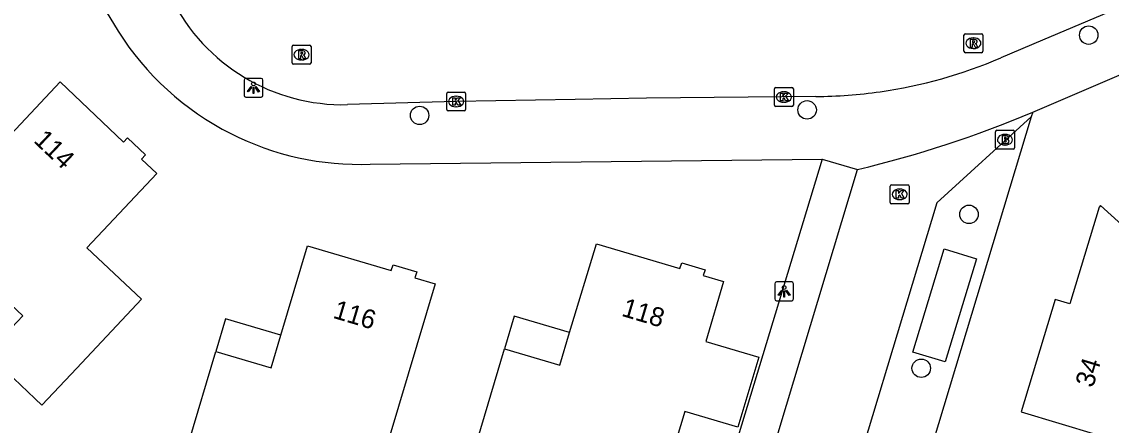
# Model space of a CAD drawing. Extents: x 157767 to 159171, y 387842 to 389425.
# Drawn here: x 158068.4 to 158126.1, y 388608.8 to 388630.1 of the extents above; entities that cross this region are included whole.
import ezdxf

# ---------------------------------------------------------------- set-up
doc = ezdxf.new("R2010")
doc.units = 0
for name, color, linetype in [('IMGEO_Boom', 7, 'Continuous'), ('IMGEO_Brandkraan', 7, 'Continuous'), ('IMGEO_Kolk', 7, 'Continuous'), ('IMGEO_Lichtpunt', 7, 'Continuous'), ('IMGEO_Pand', 7, 'Continuous'), ('IMGEO_Pand_nummerreeks', 7, 'Continuous'), ('IMGEO_Pand_overbouw', 7, 'Continuous'), ('IMGEO_Rijbaan_lokaal_open', 7, 'Continuous'), ('IMGEO_Rioolput', 7, 'Continuous'), ('IMGEO_Voetpad_open', 7, 'Continuous')]:
    doc.layers.add(name, color=color, linetype=linetype)

msp = doc.modelspace()

# ---------------------------------------------------------------- linework, layer by layer
at = {"layer": 'IMGEO_Boom'}
for centre in [(158124.95, 388629.419), (158089.511, 388625.171), (158110.036, 388625.462), (158118.608, 388619.933), (158116.078, 388611.787)]:
    msp.add_circle(centre, 0.489, dxfattribs=at)
at = {"layer": 'IMGEO_Brandkraan'}
for p, q in [((158120.014, 388623.457), (158120.014, 388624.309)), ((158120.089, 388624.383), (158120.941, 388624.383)), ((158120.502, 388624.163), (158120.527, 388624.163)), ((158121.015, 388624.309), (158121.015, 388623.457)), ((158120.941, 388623.383), (158120.089, 388623.383)), ((158120.525, 388623.603), (158120.5, 388623.603))]:
    msp.add_line(p, q, dxfattribs=at)
for points in [[(158120.014, 388623.457), (158120.014, 388624.309)], [(158120.089, 388624.383), (158120.941, 388624.383)], [(158120.362, 388624.083), (158120.362, 388623.683), (158120.575, 388623.683)], [(158120.593, 388624.083), (158120.362, 388624.083)], [(158120.541, 388624.002), (158120.487, 388624.002), (158120.487, 388623.926)], [(158120.487, 388623.926), (158120.54, 388623.926)], [(158121.015, 388624.309), (158121.015, 388623.457)], [(158120.941, 388623.383), (158120.089, 388623.383)], [(158120.549, 388623.85), (158120.487, 388623.85), (158120.487, 388623.769)], [(158120.487, 388623.769), (158120.549, 388623.769)]]:
    msp.add_lwpolyline(points, dxfattribs=at)
for centre, radius, start, end in [((158120.091, 388624.307), 0.0765, 91.55205, 178.44795), ((158120.091, 388624.307), 0.0765, 91.55205, 178.44795), ((158120.542, 388623.964), 0.0379, 267.82845, 90.93552), ((158120.597, 388623.938), 0.145, 59.4692, 91.53667), ((158120.622, 388623.985), 0.0922, 285.51372, 58.15012), ((158120.939, 388624.307), 0.0765, 1.55205, 88.44795), ((158120.939, 388624.307), 0.0765, 1.55205, 88.44795), ((158120.091, 388623.459), 0.0765, 181.55205, 268.44795), ((158120.091, 388623.459), 0.0765, 181.55205, 268.44795), ((158120.55, 388623.809), 0.0404, 269.87594, 90.50774), ((158120.581, 388623.934), 0.251, 268.66757, 293.53466), ((158120.627, 388623.793), 0.105, 301.31148, 78.98903), ((158120.939, 388623.459), 0.0765, 271.55205, 358.44795), ((158120.939, 388623.459), 0.0765, 271.55205, 358.44795)]:
    msp.add_arc(centre, radius, start, end, dxfattribs=at)
for centre, major_axis, ratio, start_param, end_param in [((158120.501, 388623.883), (-0.387, 0.002), 0.722429, 4.712389, 7.853982), ((158120.526, 388623.883), (-0.39, 0.002), 0.717154, 1.570796, 4.712389)]:
    msp.add_ellipse(centre, major_axis=major_axis, ratio=ratio, start_param=start_param, end_param=end_param, dxfattribs=at)
at = {"layer": 'IMGEO_Kolk'}
for p, q in [((158090.946, 388625.48), (158090.946, 388626.332)), ((158091.021, 388626.406), (158091.873, 388626.406)), ((158091.947, 388626.332), (158091.947, 388625.48)), ((158108.304, 388625.718), (158108.304, 388626.57)), ((158108.379, 388626.644), (158109.231, 388626.644)), ((158108.792, 388626.424), (158108.817, 388626.424)), ((158109.305, 388626.57), (158109.305, 388625.718)), ((158091.434, 388626.186), (158091.459, 388626.186)), ((158108.815, 388625.864), (158108.79, 388625.864)), ((158091.873, 388625.406), (158091.021, 388625.406)), ((158091.457, 388625.626), (158091.432, 388625.626)), ((158109.231, 388625.644), (158108.379, 388625.644)), ((158114.436, 388620.564), (158114.436, 388621.416)), ((158114.511, 388621.49), (158115.363, 388621.49)), ((158114.924, 388621.27), (158114.949, 388621.27)), ((158115.437, 388621.416), (158115.437, 388620.564)), ((158115.363, 388620.49), (158114.511, 388620.49)), ((158114.947, 388620.71), (158114.922, 388620.71))]:
    msp.add_line(p, q, dxfattribs=at)
for points in [[(158090.946, 388625.48), (158090.946, 388626.332)], [(158091.021, 388626.406), (158091.873, 388626.406)], [(158091.947, 388626.332), (158091.947, 388625.48)], [(158108.304, 388625.718), (158108.304, 388626.57)], [(158108.379, 388626.644), (158109.231, 388626.644)], [(158108.625, 388626.344), (158108.748, 388626.344), (158108.748, 388626.193), (158108.878, 388626.344), (158109.042, 388626.344), (158108.896, 388626.193), (158109.049, 388625.944), (158108.897, 388625.944), (158108.812, 388626.108), (158108.748, 388626.041), (158108.748, 388625.944), (158108.625, 388625.944), (158108.625, 388626.344)], [(158109.305, 388626.57), (158109.305, 388625.718)], [(158091.267, 388626.106), (158091.39, 388626.106), (158091.39, 388625.955), (158091.52, 388626.106), (158091.684, 388626.106), (158091.538, 388625.955), (158091.691, 388625.706), (158091.539, 388625.706), (158091.454, 388625.87), (158091.39, 388625.803), (158091.39, 388625.706), (158091.267, 388625.706), (158091.267, 388626.106)], [(158091.873, 388625.406), (158091.021, 388625.406)], [(158109.231, 388625.644), (158108.379, 388625.644)], [(158114.436, 388620.564), (158114.436, 388621.416)], [(158114.511, 388621.49), (158115.363, 388621.49)], [(158114.757, 388621.19), (158114.88, 388621.19), (158114.88, 388621.039), (158115.01, 388621.19), (158115.174, 388621.19), (158115.028, 388621.039), (158115.181, 388620.79), (158115.029, 388620.79), (158114.944, 388620.954), (158114.88, 388620.887), (158114.88, 388620.79), (158114.757, 388620.79), (158114.757, 388621.19)], [(158115.437, 388621.416), (158115.437, 388620.564)], [(158115.363, 388620.49), (158114.511, 388620.49)]]:
    msp.add_lwpolyline(points, dxfattribs=at)
for centre, start, end in [((158091.023, 388626.33), 91.55205, 178.44795), ((158091.023, 388626.33), 91.55205, 178.44795), ((158091.871, 388626.33), 1.55205, 88.44795), ((158091.871, 388626.33), 1.55205, 88.44795), ((158108.381, 388626.568), 91.55205, 178.44795), ((158108.381, 388626.568), 91.55205, 178.44795), ((158109.229, 388626.568), 1.55205, 88.44795), ((158109.229, 388626.568), 1.55205, 88.44795), ((158108.381, 388625.72), 181.55205, 268.44795), ((158108.381, 388625.72), 181.55205, 268.44795), ((158109.229, 388625.72), 271.55205, 358.44795), ((158109.229, 388625.72), 271.55205, 358.44795), ((158091.023, 388625.482), 181.55205, 268.44795), ((158091.023, 388625.482), 181.55205, 268.44795), ((158091.871, 388625.482), 271.55205, 358.44795), ((158091.871, 388625.482), 271.55205, 358.44795), ((158114.513, 388621.414), 91.55205, 178.44795), ((158114.513, 388621.414), 91.55205, 178.44795), ((158115.361, 388621.414), 1.55205, 88.44795), ((158115.361, 388621.414), 1.55205, 88.44795), ((158114.513, 388620.566), 181.55205, 268.44795), ((158114.513, 388620.566), 181.55205, 268.44795), ((158115.361, 388620.566), 271.55205, 358.44795), ((158115.361, 388620.566), 271.55205, 358.44795)]:
    msp.add_arc(centre, 0.0765, start, end, dxfattribs=at)
for centre, major_axis, ratio, start_param, end_param in [((158108.791, 388626.144), (-0.387, 0.002), 0.722429, 4.712389, 7.853982), ((158108.816, 388626.144), (-0.39, 0.002), 0.717154, 1.570796, 4.712389), ((158091.433, 388625.906), (-0.387, 0.002), 0.722429, 4.712389, 7.853982), ((158091.458, 388625.906), (-0.39, 0.002), 0.717154, 1.570796, 4.712389), ((158114.923, 388620.99), (-0.387, 0.002), 0.722429, 4.712389, 7.853982), ((158114.948, 388620.99), (-0.39, 0.002), 0.717154, 1.570796, 4.712389)]:
    msp.add_ellipse(centre, major_axis=major_axis, ratio=ratio, start_param=start_param, end_param=end_param, dxfattribs=at)
at = {"layer": 'IMGEO_Lichtpunt'}
for p, q in [((158080.214, 388627.036), (158080.214, 388626.229)), ((158080.214, 388627.036), (158080.214, 388626.229)), ((158081.116, 388627.131), (158080.308, 388627.131)), ((158081.116, 388627.131), (158080.308, 388627.131)), ((158081.21, 388626.229), (158081.21, 388627.036)), ((158081.21, 388626.229), (158081.21, 388627.036)), ((158080.308, 388626.135), (158081.116, 388626.135)), ((158080.308, 388626.135), (158081.116, 388626.135)), ((158108.318, 388616.261), (158108.318, 388615.454)), ((158108.318, 388616.261), (158108.318, 388615.454)), ((158109.22, 388616.356), (158108.412, 388616.356)), ((158109.22, 388616.356), (158108.412, 388616.356)), ((158109.314, 388615.454), (158109.314, 388616.261)), ((158109.314, 388615.454), (158109.314, 388616.261)), ((158108.412, 388615.36), (158109.22, 388615.36)), ((158108.412, 388615.36), (158109.22, 388615.36))]:
    msp.add_line(p, q, dxfattribs=at)
for points in [[(158080.588, 388626.7), (158080.627, 388626.672), (158080.439, 388626.41), (158080.401, 388626.437), (158080.588, 388626.7)], [(158080.69, 388626.652), (158080.737, 388626.652), (158080.737, 388626.33), (158080.69, 388626.33), (158080.69, 388626.652)], [(158080.8, 388626.672), (158080.838, 388626.699), (158081.025, 388626.437), (158080.986, 388626.409), (158080.8, 388626.672)], [(158108.692, 388615.925), (158108.731, 388615.897), (158108.543, 388615.635), (158108.505, 388615.662), (158108.692, 388615.925)], [(158108.794, 388615.877), (158108.841, 388615.877), (158108.841, 388615.555), (158108.794, 388615.555), (158108.794, 388615.877)], [(158108.904, 388615.897), (158108.942, 388615.924), (158109.129, 388615.662), (158109.09, 388615.634), (158108.904, 388615.897)]]:
    msp.add_lwpolyline(points, dxfattribs=at)
for centre in [(158080.713, 388626.834), (158108.817, 388616.059)]:
    msp.add_circle(centre, 0.0994, dxfattribs=at)
for centre, start, end in [((158080.308, 388627.036), 90, 180), ((158080.308, 388627.036), 90, 180), ((158081.116, 388627.036), 0, 90), ((158081.116, 388627.036), 0, 90), ((158080.308, 388626.229), 180, 270), ((158080.308, 388626.229), 180, 270), ((158081.116, 388626.229), 270, 0), ((158081.116, 388626.229), 270, 360), ((158108.412, 388616.261), 90, 180), ((158108.412, 388616.261), 90, 180), ((158109.22, 388616.261), 0, 90), ((158109.22, 388616.261), 0, 90), ((158108.412, 388615.454), 180, 270), ((158108.412, 388615.454), 180, 270), ((158109.22, 388615.454), 270, 0), ((158109.22, 388615.454), 270, 360)]:
    msp.add_arc(centre, 0.0946, start, end, dxfattribs=at)
at = {"layer": 'IMGEO_Pand'}
for points in [[(158067.64, 388611.59), (158067.598, 388613.613), (158068.491, 388614.561), (158065.977, 388616.929), (158062.894, 388613.658), (158058.049, 388618.224), (158060.19, 388620.454), (158063.653, 388624.06), (158065.8, 388621.999), (158067.059, 388623.331), (158070.47, 388626.939), (158073.821, 388623.759), (158074.041, 388623.991), (158074.994, 388623.089), (158074.774, 388622.857), (158075.586, 388622.087), (158071.89, 388618.165), (158074.785, 388615.436), (158071.356, 388611.798), (158069.503, 388609.833), (158067.64, 388611.59)], [(158132.014, 388603.229), (158132.651, 388605.327), (158133.533, 388608.235), (158131.528, 388608.844), (158132.654, 388612.554), (158131.877, 388612.79), (158132.331, 388614.286), (158125.578, 388620.401), (158125.498, 388620.309), (158123.945, 388615.198), (158123.177, 388615.431), (158121.373, 388609.487), (158125.364, 388608.277), (158126.349, 388607.978), (158125.508, 388605.204)], [(158076.409, 388604.909), (158077.293, 388607.881), (158078.719, 388612.673), (158081.643, 388611.804), (158082.157, 388613.529), (158083.569, 388618.273), (158088.009, 388616.965), (158088.103, 388617.258), (158089.358, 388616.898), (158089.258, 388616.577), (158090.34, 388616.259), (158088.902, 388611.471), (158087.362, 388606.343), (158082.858, 388607.684), (158081.574, 388603.371), (158076.409, 388604.909)], [(158094.472, 388604.207), (158093.645, 388601.415), (158090.868, 388602.238), (158091.697, 388605.035), (158094.005, 388612.821), (158096.93, 388611.955), (158097.451, 388613.678), (158098.871, 388618.376), (158103.3, 388617.065), (158103.399, 388617.364), (158104.63, 388616.998), (158104.538, 388616.692), (158105.609, 388616.37), (158104.665, 388613.208), (158107.469, 388612.371), (158106.361, 388608.662), (158103.557, 388609.499), (158102.649, 388606.457), (158098.15, 388607.799), (158096.865, 388603.493), (158094.472, 388604.207)]]:
    msp.add_lwpolyline(points, dxfattribs=at)
at = {"layer": 'IMGEO_Pand_overbouw'}
for points in [[(158078.719, 388612.673), (158081.643, 388611.804), (158082.157, 388613.529), (158079.233, 388614.398)], [(158097.451, 388613.678), (158094.512, 388614.536), (158094.005, 388612.821), (158096.93, 388611.955)]]:
    msp.add_lwpolyline(points, close=True, dxfattribs=at)
at = {"layer": 'IMGEO_Rijbaan_lokaal_open'}
for points in [[(158126.853, 388631.015), (158125.679, 388630.492), (158122.493, 388629.144), (158120.299, 388628.215)], [(158110.492, 388626.173), (158101.53, 388626.077), (158097.745, 388626.013), (158091.452, 388625.907), (158085.699, 388625.739)], [(158121.909, 388625.102), (158116.908, 388620.535), (158111.159, 388601.555)], [(158121.982, 388625.344), (158121.909, 388625.102)], [(158106.836, 388602.865), (158112.707, 388622.305)]]:
    msp.add_lwpolyline(points, dxfattribs=at)
for centre, radius, start, end in [((158085.464, 388635.908), 10.172, 206.56632, 271.32398), ((158110.373, 388651.368), 25.191, 278.06551, 293.20635), ((158110.356, 388651.184), 25.012, 270.31175, 278.16228), ((158098.883, 388680.169), 59.493, 283.43648, 292.8468)]:
    msp.add_arc(centre, radius, start, end, dxfattribs=at)
at = {"layer": 'IMGEO_Rioolput'}
for p, q in [((158118.341, 388628.565), (158118.341, 388629.417)), ((158118.416, 388629.491), (158119.268, 388629.491)), ((158118.829, 388629.271), (158118.854, 388629.271)), ((158119.342, 388629.417), (158119.342, 388628.565)), ((158082.758, 388627.958), (158082.758, 388628.81)), ((158082.833, 388628.884), (158083.685, 388628.884)), ((158083.246, 388628.664), (158083.271, 388628.664)), ((158083.759, 388628.81), (158083.759, 388627.958)), ((158118.852, 388628.711), (158118.827, 388628.711)), ((158083.269, 388628.104), (158083.244, 388628.104)), ((158119.268, 388628.491), (158118.416, 388628.491)), ((158083.685, 388627.884), (158082.833, 388627.884))]:
    msp.add_line(p, q, dxfattribs=at)
for points in [[(158118.341, 388628.565), (158118.341, 388629.417)], [(158118.416, 388629.491), (158119.268, 388629.491)], [(158118.93, 388629.189), (158118.678, 388629.191), (158118.678, 388628.791)], [(158118.856, 388629.11), (158118.802, 388629.11), (158118.802, 388629.029)], [(158119.342, 388629.417), (158119.342, 388628.565)], [(158082.758, 388627.958), (158082.758, 388628.81)], [(158082.833, 388628.884), (158083.685, 388628.884)], [(158083.347, 388628.582), (158083.095, 388628.584), (158083.095, 388628.184)], [(158083.759, 388628.81), (158083.759, 388627.958)], [(158118.678, 388628.791), (158118.802, 388628.791), (158118.802, 388628.953), (158118.813, 388628.953)], [(158118.802, 388629.029), (158118.854, 388629.029)], [(158118.86, 388628.924), (158118.931, 388628.791), (158119.071, 388628.791), (158119.006, 388628.917)], [(158083.095, 388628.184), (158083.219, 388628.184), (158083.219, 388628.346), (158083.23, 388628.346)], [(158083.273, 388628.503), (158083.219, 388628.503), (158083.219, 388628.422)], [(158083.219, 388628.422), (158083.271, 388628.422)], [(158083.277, 388628.317), (158083.348, 388628.184), (158083.488, 388628.184), (158083.423, 388628.31)], [(158119.268, 388628.491), (158118.416, 388628.491)], [(158083.685, 388627.884), (158082.833, 388627.884)]]:
    msp.add_lwpolyline(points, dxfattribs=at)
for centre, radius, start, end in [((158118.418, 388629.415), 0.0765, 91.55205, 178.44795), ((158118.418, 388629.415), 0.0765, 91.55205, 178.44795), ((158118.862, 388629.014), 0.0964, 77.00612, 93.18647), ((158118.876, 388629.071), 0.0378, 276.66336, 79.67722), ((158118.929, 388629.079), 0.109, 350.36119, 89.41601), ((158119.266, 388629.415), 0.0765, 1.55205, 88.44795), ((158119.266, 388629.415), 0.0765, 1.55205, 88.44795), ((158082.835, 388628.808), 0.0765, 91.55205, 178.44795), ((158082.835, 388628.808), 0.0765, 91.55205, 178.44795), ((158083.346, 388628.472), 0.109, 350.36119, 89.41601), ((158083.683, 388628.808), 0.0765, 1.55205, 88.44795), ((158083.683, 388628.808), 0.0765, 1.55205, 88.44795), ((158118.418, 388628.567), 0.0765, 181.55205, 268.44795), ((158118.418, 388628.567), 0.0765, 181.55205, 268.44795), ((158118.812, 388628.9), 0.0533, 26.02933, 88.69889), ((158118.838, 388629.218), 0.19, 274.7715, 282.96867), ((158118.927, 388629.079), 0.112, 277.58423, 350.98172), ((158118.911, 388628.864), 0.108, 29.51342, 73.79051), ((158119.266, 388628.567), 0.0765, 271.55205, 358.44795), ((158119.266, 388628.567), 0.0765, 271.55205, 358.44795), ((158082.835, 388627.96), 0.0765, 181.55205, 268.44795), ((158082.835, 388627.96), 0.0765, 181.55205, 268.44795), ((158083.229, 388628.293), 0.0533, 26.02933, 88.69889), ((158083.255, 388628.611), 0.19, 274.7715, 282.96867), ((158083.279, 388628.407), 0.0964, 77.00612, 93.18647), ((158083.293, 388628.464), 0.0378, 276.66336, 79.67722), ((158083.344, 388628.472), 0.112, 277.58423, 350.98172), ((158083.328, 388628.257), 0.108, 29.51342, 73.79051), ((158083.683, 388627.96), 0.0765, 271.55205, 358.44795), ((158083.683, 388627.96), 0.0765, 271.55205, 358.44795)]:
    msp.add_arc(centre, radius, start, end, dxfattribs=at)
for centre, major_axis, ratio, start_param, end_param in [((158118.828, 388628.991), (-0.387, 0.002), 0.722429, 4.712389, 7.853982), ((158118.853, 388628.991), (-0.39, 0.002), 0.717154, 1.570796, 4.712389), ((158083.245, 388628.384), (-0.387, 0.002), 0.722429, 4.712389, 7.853982), ((158083.27, 388628.384), (-0.39, 0.002), 0.717154, 1.570796, 4.712389)]:
    msp.add_ellipse(centre, major_axis=major_axis, ratio=ratio, start_param=start_param, end_param=end_param, dxfattribs=at)
at = {"layer": 'IMGEO_Voetpad_open'}
for points in [[(158121.982, 388625.344), (158206.335, 388661.478), (158218.193, 388666.558)], [(158065.111, 388643.432), (158073.538, 388629.633)], [(158121.909, 388625.102), (158108.361, 388580.257)], [(158086.888, 388622.589), (158110.825, 388622.857)], [(158110.825, 388622.857), (158096.009, 388573.979), (158095.729, 388573.163), (158091.518, 388574.404)], [(158110.825, 388622.857), (158112.707, 388622.305)], [(158115.635, 388612.631), (158117.29, 388618.103), (158119.01, 388617.581), (158117.343, 388612.122), (158115.635, 388612.631)]]:
    msp.add_lwpolyline(points, dxfattribs=at)
for centre, radius, start, end in [((158086.295, 388637.686), 15.086, 212.2641, 243.27358), ((158086.302, 388637.506), 14.928, 242.93728, 272.25026)]:
    msp.add_arc(centre, radius, start, end, dxfattribs=at)

# ---------------------------------------------------------------- texts
at = {"layer": 'IMGEO_Pand_nummerreeks'}
for s, rotation, p in [('114', 316.49982, (158069.02, 388623.792)), ('116', 343.43516, (158084.874, 388614.463)), ('118', 343.4186, (158100.16, 388614.57)), ('34', 73.11514, (158125.173, 388610.716))]:
    msp.add_text(s, height=1, rotation=rotation, dxfattribs=at).set_placement(p)

doc.saveas('drawing.dxf')
